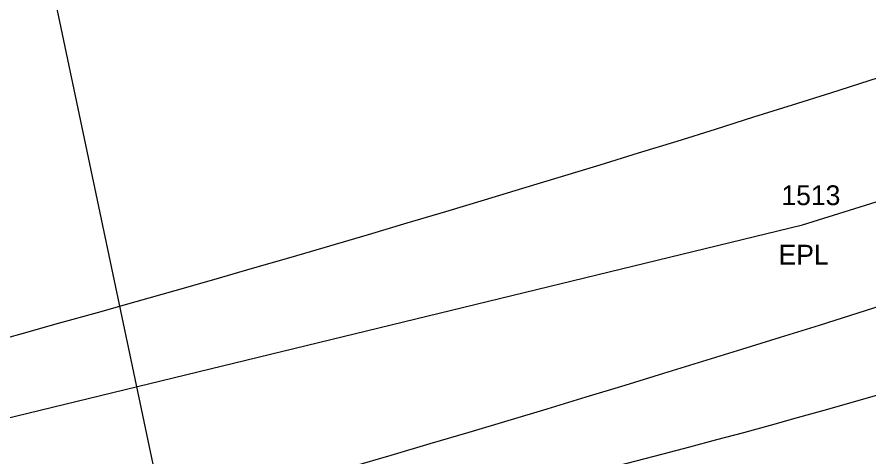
# Model space of a CAD drawing. Extents: x 1964982 to 1970452, y 1116335 to 1119906.
# Drawn here: x 1966676.88 to 1966719.86, y 1117427.62 to 1117449.81 of the extents above; entities that cross this region are included whole.
import ezdxf

# ---------------------------------------------------------------- set-up
doc = ezdxf.new("R2010")
doc.units = 0
for name, color, linetype in [('RD_EX_DV_Prop', 7, 'Continuous'), ('RD_EX_Road', 7, 'Continuous'), ('RD_EX_Road_txCode', 7, 'Continuous'), ('RD_EX_RW', 7, 'Continuous'), ('RD_HC_CL', 7, 'Continuous'), ('RD_HC_CL_Rel', 7, 'Continuous'), ('RD_HC_Data', 7, 'Continuous'), ('RD_PD_Final_TrvlWay', 7, 'Continuous'), ('RD_SMD_Locator', 7, 'Continuous')]:
    doc.layers.add(name, color=color, linetype=linetype)

msp = doc.modelspace()

# ---------------------------------------------------------------- linework, layer by layer
at = {"layer": 'RD_EX_DV_Prop'}
msp.add_arc((1966579.594, 1117921.318), 510.35, 281.90473, 291.99584, dxfattribs=at)
at = {"layer": 'RD_EX_Road'}
msp.add_lwpolyline([(1966297.245, 1117343.102), (1966344.085, 1117357.038), (1966390.785, 1117368.561), (1966438.122, 1117379.082), (1966484.547, 1117389.131), (1966531.199, 1117398.733), (1966578.388, 1117408.593), (1966604.527, 1117414.058), (1966624.537, 1117418.323), (1966671.319, 1117428.348), (1966716.506, 1117439.32), (1966736.604, 1117445.59), (1966754.133, 1117451.442), (1966759.658, 1117453.517), (1966769.512, 1117457.475)], dxfattribs=at)
at = {"layer": 'RD_EX_RW'}
msp.add_lwpolyline([(1966297.245, 1117343.102), (1966344.085, 1117357.038), (1966390.785, 1117368.561), (1966438.122, 1117379.082), (1966484.547, 1117389.131), (1966531.199, 1117398.733), (1966578.388, 1117408.593), (1966604.527, 1117414.058), (1966624.537, 1117418.323), (1966671.319, 1117428.348), (1966716.506, 1117439.32), (1966736.604, 1117445.59), (1966754.133, 1117451.442), (1966759.658, 1117453.517), (1966769.512, 1117457.475)], dxfattribs=at)
at = {"layer": 'RD_HC_CL'}
msp.add_arc((1966579.594, 1117921.318), 510.35, 281.90472, 291.99584, dxfattribs=at)
at = {"layer": 'RD_HC_CL_Rel'}
msp.add_arc((1966373.74, 1118527.456), 1145.915, 281.904723, 295.046328, dxfattribs=at)
at = {"layer": 'RD_HC_Data'}
msp.add_line((1966684.871, 1117421.945), (1966664.447, 1117518.825), dxfattribs=at)
at = {"layer": 'RD_PD_Final_TrvlWay'}
for radius in [1134.915, 1156.915]:
    msp.add_arc((1966373.74, 1118527.456), radius, 281.904723, 295.046328, dxfattribs=at)
at = {"layer": 'RD_SMD_Locator'}
msp.add_circle((1966716.506, 1117439.32), 0.001, dxfattribs=at)
msp.add_circle((1966716.506, 1117439.32), 0.001, dxfattribs=at)

# ---------------------------------------------------------------- texts
at = {"layer": 'RD_EX_Road_txCode'}
for s, p in [('1513', (1966715.443, 1117440.32)), ('1513', (1966715.443, 1117440.32)), ('EPL', (1966715.301, 1117437.32)), ('EPL', (1966715.301, 1117437.32))]:
    msp.add_text(s, height=1, dxfattribs=at).set_placement(p)

doc.saveas('drawing.dxf')
